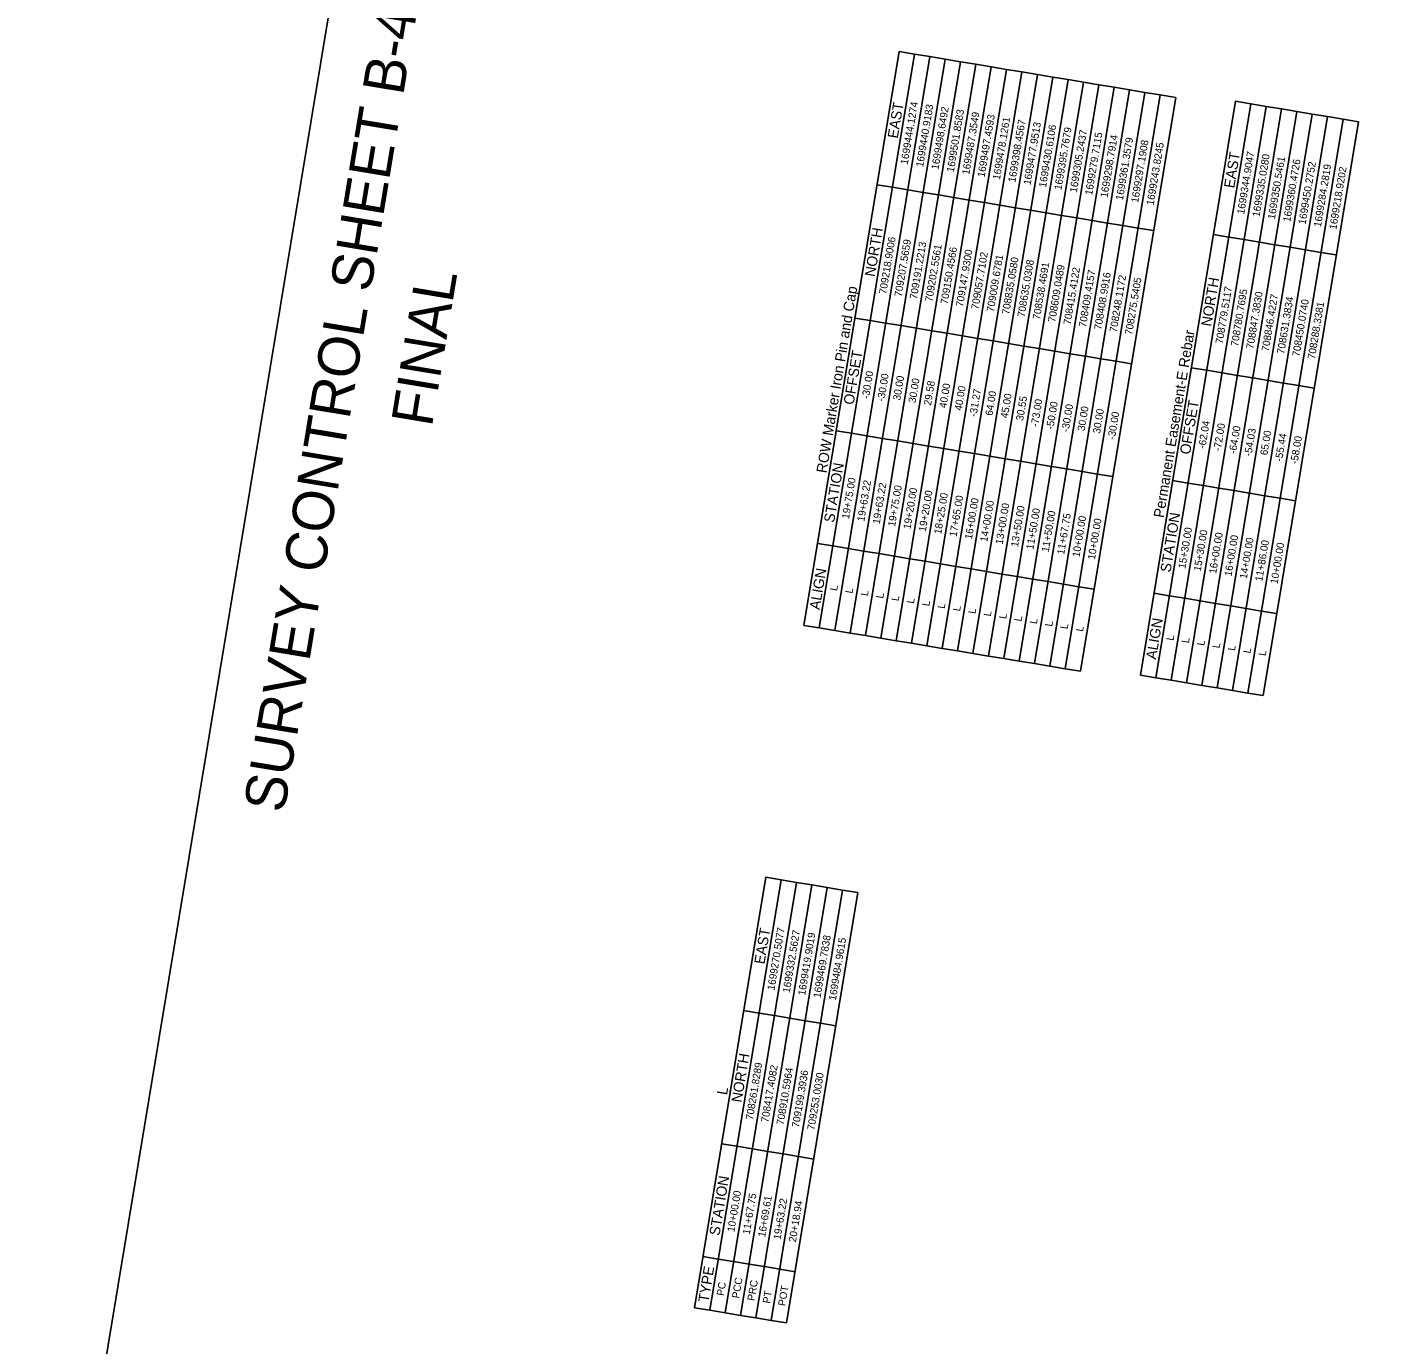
# Model space of a CAD drawing. Extents: x 1698609 to 1700392, y 707479 to 710040.
# Drawn here: x 1698609 to 1699524, y 708282 to 709170 of the extents above; entities that cross this region are included whole.
import ezdxf

# ---------------------------------------------------------------- set-up
doc = ezdxf.new("R2010")
doc.units = 0
for name, color, linetype in [('CTL Sheet Border CELL', 7, 'Continuous'), ('CTL Sheet Notes CELL', 7, 'Continuous'), ('CTL Sheet Table Cell', 7, 'Continuous'), ('CTL Sheet Text', 7, 'Continuous')]:
    doc.layers.add(name, color=color, linetype=linetype)

msp = doc.modelspace()

# ---------------------------------------------------------------- linework, layer by layer
at = {"layer": 'CTL Sheet Border CELL'}
msp.add_lwpolyline([(1698950.4, 710011.31), (1698609.09, 707952.45), (1700050.28, 707713.53), (1700391.59, 709772.4)], close=True, dxfattribs=at)
at = {"layer": 'CTL Sheet Table Cell'}
for p, q in [((1699132.73, 708766.82), (1699196.83, 709153.54)), ((1699143.08, 708765.1), (1699207.19, 709151.82)), ((1699153.44, 708763.39), (1699217.55, 709150.11)), ((1699163.8, 708761.67), (1699227.91, 709148.39)), ((1699196.83, 709153.54), (1699207.19, 709151.82)), ((1699207.19, 709151.82), (1699217.55, 709150.11)), ((1699217.55, 709150.11), (1699227.91, 709148.39)), ((1699227.91, 709148.39), (1699238.27, 709146.67)), ((1699174.16, 708759.95), (1699238.27, 709146.67)), ((1699184.52, 708758.23), (1699248.63, 709144.96)), ((1699194.88, 708756.52), (1699258.99, 709143.24)), ((1699205.24, 708754.8), (1699269.35, 709141.52)), ((1699215.59, 708753.08), (1699279.7, 709139.8)), ((1699225.95, 708751.37), (1699290.06, 709138.09)), ((1699238.27, 709146.67), (1699248.63, 709144.96)), ((1699248.63, 709144.96), (1699258.99, 709143.24)), ((1699258.99, 709143.24), (1699269.35, 709141.52)), ((1699269.35, 709141.52), (1699279.7, 709139.8)), ((1699279.7, 709139.8), (1699290.06, 709138.09)), ((1699290.06, 709138.09), (1699300.42, 709136.37)), ((1699236.31, 708749.65), (1699300.42, 709136.37)), ((1699246.67, 708747.93), (1699310.78, 709134.65)), ((1699257.03, 708746.21), (1699321.14, 709132.94)), ((1699267.39, 708744.5), (1699331.5, 709131.22)), ((1699277.75, 708742.78), (1699341.86, 709129.5)), ((1699300.42, 709136.37), (1699310.78, 709134.65)), ((1699310.78, 709134.65), (1699321.14, 709132.94)), ((1699321.14, 709132.94), (1699331.5, 709131.22)), ((1699331.5, 709131.22), (1699341.86, 709129.5)), ((1699341.86, 709129.5), (1699352.21, 709127.78)), ((1699288.11, 708741.06), (1699352.21, 709127.78)), ((1699298.46, 708739.34), (1699362.57, 709126.07)), ((1699308.82, 708737.63), (1699372.93, 709124.35)), ((1699319.18, 708735.91), (1699383.29, 709122.63)), ((1699352.21, 709127.78), (1699362.57, 709126.07)), ((1699359.49, 708733.3), (1699423.6, 709120.02)), ((1699362.57, 709126.07), (1699372.93, 709124.35)), ((1699372.93, 709124.35), (1699383.29, 709122.63)), ((1699423.6, 709120.02), (1699433.96, 709118.31)), ((1699369.85, 708731.58), (1699433.96, 709118.31)), ((1699380.21, 708729.87), (1699444.32, 709116.59)), ((1699390.57, 708728.15), (1699454.68, 709114.87)), ((1699400.93, 708726.43), (1699465.04, 709113.15)), ((1699411.29, 708724.71), (1699475.39, 709111.44)), ((1699433.96, 709118.31), (1699444.32, 709116.59)), ((1699444.32, 709116.59), (1699454.68, 709114.87)), ((1699454.68, 709114.87), (1699465.04, 709113.15)), ((1699465.04, 709113.15), (1699475.39, 709111.44)), ((1699475.39, 709111.44), (1699485.75, 709109.72)), ((1699421.64, 708723), (1699485.75, 709109.72)), ((1699432, 708721.28), (1699496.11, 709108)), ((1699442.36, 708719.56), (1699506.47, 709106.28)), ((1699485.75, 709109.72), (1699496.11, 709108)), ((1699496.11, 709108), (1699506.47, 709106.28)), ((1699181.95, 709063.77), (1699192.31, 709062.05)), ((1699192.31, 709062.05), (1699202.67, 709060.33)), ((1699202.67, 709060.33), (1699213.03, 709058.62)), ((1699213.03, 709058.62), (1699223.39, 709056.9)), ((1699223.39, 709056.9), (1699233.75, 709055.18)), ((1699233.75, 709055.18), (1699244.1, 709053.46)), ((1699244.1, 709053.46), (1699254.46, 709051.75)), ((1699254.46, 709051.75), (1699264.82, 709050.03)), ((1699264.82, 709050.03), (1699275.18, 709048.31)), ((1699275.18, 709048.31), (1699285.54, 709046.6)), ((1699285.54, 709046.6), (1699295.9, 709044.88)), ((1699295.9, 709044.88), (1699306.26, 709043.16)), ((1699306.26, 709043.16), (1699316.61, 709041.44)), ((1699316.61, 709041.44), (1699326.97, 709039.73)), ((1699326.97, 709039.73), (1699337.33, 709038.01)), ((1699337.33, 709038.01), (1699347.69, 709036.29)), ((1699347.69, 709036.29), (1699358.05, 709034.57)), ((1699358.05, 709034.57), (1699368.41, 709032.86)), ((1699408.72, 709030.25), (1699419.08, 709028.53)), ((1699419.08, 709028.53), (1699429.44, 709026.81)), ((1699429.44, 709026.81), (1699439.79, 709025.1)), ((1699439.79, 709025.1), (1699450.15, 709023.38)), ((1699450.15, 709023.38), (1699460.51, 709021.66)), ((1699460.51, 709021.66), (1699470.87, 709019.94)), ((1699470.87, 709019.94), (1699481.23, 709018.23)), ((1699481.23, 709018.23), (1699491.59, 709016.51)), ((1699167.07, 708973.99), (1699177.43, 708972.28)), ((1699177.43, 708972.28), (1699187.79, 708970.56)), ((1699187.79, 708970.56), (1699198.15, 708968.84)), ((1699198.15, 708968.84), (1699208.5, 708967.12)), ((1699208.5, 708967.12), (1699218.86, 708965.41)), ((1699218.86, 708965.41), (1699229.22, 708963.69)), ((1699229.22, 708963.69), (1699239.58, 708961.97)), ((1699239.58, 708961.97), (1699249.94, 708960.25)), ((1699249.94, 708960.25), (1699260.3, 708958.54)), ((1699260.3, 708958.54), (1699270.66, 708956.82)), ((1699270.66, 708956.82), (1699281.01, 708955.1)), ((1699281.01, 708955.1), (1699291.37, 708953.39)), ((1699291.37, 708953.39), (1699301.73, 708951.67)), ((1699301.73, 708951.67), (1699312.09, 708949.95)), ((1699312.09, 708949.95), (1699322.45, 708948.23)), ((1699322.45, 708948.23), (1699332.81, 708946.52)), ((1699332.81, 708946.52), (1699343.17, 708944.8)), ((1699343.17, 708944.8), (1699353.53, 708943.08)), ((1699393.84, 708940.47), (1699404.19, 708938.76)), ((1699404.19, 708938.76), (1699414.55, 708937.04)), ((1699414.55, 708937.04), (1699424.91, 708935.32)), ((1699424.91, 708935.32), (1699435.27, 708933.6)), ((1699435.27, 708933.6), (1699445.63, 708931.89)), ((1699445.63, 708931.89), (1699455.99, 708930.17)), ((1699455.99, 708930.17), (1699466.35, 708928.45)), ((1699466.35, 708928.45), (1699476.71, 708926.74)), ((1699154.48, 708898.03), (1699164.84, 708896.31)), ((1699164.84, 708896.31), (1699175.19, 708894.59)), ((1699175.19, 708894.59), (1699185.55, 708892.88)), ((1699185.55, 708892.88), (1699195.91, 708891.16)), ((1699195.91, 708891.16), (1699206.27, 708889.44)), ((1699206.27, 708889.44), (1699216.63, 708887.73)), ((1699216.63, 708887.73), (1699226.99, 708886.01)), ((1699226.99, 708886.01), (1699237.35, 708884.29)), ((1699237.35, 708884.29), (1699247.7, 708882.57)), ((1699247.7, 708882.57), (1699258.06, 708880.86)), ((1699258.06, 708880.86), (1699268.42, 708879.14)), ((1699268.42, 708879.14), (1699278.78, 708877.42)), ((1699278.78, 708877.42), (1699289.14, 708875.71)), ((1699289.14, 708875.71), (1699299.5, 708873.99)), ((1699299.5, 708873.99), (1699309.86, 708872.27)), ((1699309.86, 708872.27), (1699320.22, 708870.55)), ((1699320.22, 708870.55), (1699330.57, 708868.84)), ((1699330.57, 708868.84), (1699340.93, 708867.12)), ((1699381.24, 708864.51), (1699391.6, 708862.79)), ((1699391.6, 708862.79), (1699401.96, 708861.08)), ((1699401.96, 708861.08), (1699412.32, 708859.36)), ((1699412.32, 708859.36), (1699422.68, 708857.64)), ((1699422.68, 708857.64), (1699433.04, 708855.92)), ((1699433.04, 708855.92), (1699443.4, 708854.21)), ((1699443.4, 708854.21), (1699453.75, 708852.49)), ((1699453.75, 708852.49), (1699464.11, 708850.77)), ((1699141.88, 708822.07), (1699152.24, 708820.35)), ((1699152.24, 708820.35), (1699162.6, 708818.63)), ((1699162.6, 708818.63), (1699172.96, 708816.91)), ((1699172.96, 708816.91), (1699183.32, 708815.2)), ((1699183.32, 708815.2), (1699193.68, 708813.48)), ((1699193.68, 708813.48), (1699204.04, 708811.76)), ((1699204.04, 708811.76), (1699214.39, 708810.05)), ((1699214.39, 708810.05), (1699224.75, 708808.33)), ((1699224.75, 708808.33), (1699235.11, 708806.61)), ((1699235.11, 708806.61), (1699245.47, 708804.89)), ((1699245.47, 708804.89), (1699255.83, 708803.18)), ((1699255.83, 708803.18), (1699266.19, 708801.46)), ((1699266.19, 708801.46), (1699276.55, 708799.74)), ((1699276.55, 708799.74), (1699286.9, 708798.03)), ((1699286.9, 708798.03), (1699297.26, 708796.31)), ((1699297.26, 708796.31), (1699307.62, 708794.59)), ((1699307.62, 708794.59), (1699317.98, 708792.87)), ((1699317.98, 708792.87), (1699328.34, 708791.16)), ((1699368.65, 708788.55), (1699379.01, 708786.83)), ((1699379.01, 708786.83), (1699389.37, 708785.11)), ((1699389.37, 708785.11), (1699399.73, 708783.39)), ((1699399.73, 708783.39), (1699410.09, 708781.68)), ((1699410.09, 708781.68), (1699420.44, 708779.96)), ((1699420.44, 708779.96), (1699430.8, 708778.24)), ((1699430.8, 708778.24), (1699441.16, 708776.53)), ((1699441.16, 708776.53), (1699451.52, 708774.81)), ((1699132.73, 708766.82), (1699143.08, 708765.1)), ((1699143.08, 708765.1), (1699153.44, 708763.39)), ((1699153.44, 708763.39), (1699163.8, 708761.67)), ((1699163.8, 708761.67), (1699174.16, 708759.95)), ((1699174.16, 708759.95), (1699184.52, 708758.23)), ((1699184.52, 708758.23), (1699194.88, 708756.52)), ((1699194.88, 708756.52), (1699205.24, 708754.8)), ((1699205.24, 708754.8), (1699215.59, 708753.08)), ((1699215.59, 708753.08), (1699225.95, 708751.37)), ((1699225.95, 708751.37), (1699236.31, 708749.65)), ((1699236.31, 708749.65), (1699246.67, 708747.93)), ((1699246.67, 708747.93), (1699257.03, 708746.21)), ((1699257.03, 708746.21), (1699267.39, 708744.5)), ((1699267.39, 708744.5), (1699277.75, 708742.78)), ((1699277.75, 708742.78), (1699288.11, 708741.06)), ((1699288.11, 708741.06), (1699298.46, 708739.34)), ((1699298.46, 708739.34), (1699308.82, 708737.63)), ((1699308.82, 708737.63), (1699319.18, 708735.91)), ((1699359.49, 708733.3), (1699369.85, 708731.58)), ((1699369.85, 708731.58), (1699380.21, 708729.87)), ((1699380.21, 708729.87), (1699390.57, 708728.15)), ((1699390.57, 708728.15), (1699400.93, 708726.43)), ((1699400.93, 708726.43), (1699411.29, 708724.71)), ((1699411.29, 708724.71), (1699421.64, 708723)), ((1699421.64, 708723), (1699432, 708721.28)), ((1699432, 708721.28), (1699442.36, 708719.56)), ((1699058.91, 708307.02), (1699106.95, 708597.07)), ((1699069.26, 708305.31), (1699117.31, 708595.35)), ((1699079.62, 708303.59), (1699127.67, 708593.64)), ((1699089.98, 708301.87), (1699138.02, 708591.92)), ((1699100.34, 708300.16), (1699148.38, 708590.21)), ((1699106.95, 708597.07), (1699117.31, 708595.35)), ((1699117.31, 708595.35), (1699127.67, 708593.64)), ((1699127.67, 708593.64), (1699138.02, 708591.92)), ((1699138.02, 708591.92), (1699148.38, 708590.21)), ((1699148.38, 708590.21), (1699158.74, 708588.49)), ((1699110.7, 708298.44), (1699158.74, 708588.49)), ((1699121.06, 708296.73), (1699169.1, 708586.77)), ((1699158.74, 708588.49), (1699169.1, 708586.77)), ((1699092.08, 708507.29), (1699102.44, 708505.58)), ((1699102.44, 708505.58), (1699112.8, 708503.86)), ((1699112.8, 708503.86), (1699123.15, 708502.15)), ((1699123.15, 708502.15), (1699133.51, 708500.43)), ((1699133.51, 708500.43), (1699143.87, 708498.71)), ((1699143.87, 708498.71), (1699154.23, 708497)), ((1699077.21, 708417.52), (1699087.57, 708415.8)), ((1699087.57, 708415.8), (1699097.93, 708414.08)), ((1699097.93, 708414.08), (1699108.28, 708412.37)), ((1699108.28, 708412.37), (1699118.64, 708410.65)), ((1699118.64, 708410.65), (1699129, 708408.94)), ((1699129, 708408.94), (1699139.36, 708407.22)), ((1699064.63, 708341.55), (1699074.98, 708339.83)), ((1699074.98, 708339.83), (1699085.34, 708338.12)), ((1699085.34, 708338.12), (1699095.7, 708336.4)), ((1699095.7, 708336.4), (1699106.06, 708334.69)), ((1699106.06, 708334.69), (1699116.42, 708332.97)), ((1699116.42, 708332.97), (1699126.78, 708331.26)), ((1699058.91, 708307.02), (1699069.26, 708305.31)), ((1699069.26, 708305.31), (1699079.62, 708303.59)), ((1699079.62, 708303.59), (1699089.98, 708301.87)), ((1699089.98, 708301.87), (1699100.34, 708300.16)), ((1699100.34, 708300.16), (1699110.7, 708298.44)), ((1699110.7, 708298.44), (1699121.06, 708296.73))]:
    msp.add_line(p, q, dxfattribs=at)

# ---------------------------------------------------------------- texts
at = {"layer": 'CTL Sheet Border CELL'}
for s, height, p in [('SURVEY CONTROL SHEET B-4799', 27.8261, (1698782.33, 708639.88)), ('FINAL', 27.826, (1698881.86, 708899.95))]:
    msp.add_text(s, height=height, rotation=80.58737, dxfattribs=at).set_placement(p)
at = {"layer": 'CTL Sheet Notes CELL'}
for s, rotation, p in [('EAST', 80.58737, (1699195.94, 709094.66)), ('EAST', 80.58737, (1699422.71, 709061.14)), ('NORTH', 80.58737, (1699180.49, 709001.46)), ('NORTH', 80.58737, (1699407.26, 708967.94)), ('ROW Marker Iron Pin and Cap', 80.58737, (1699147.91, 708869.12)), ('Permanent Easement-E Rebar', 80.58737, (1699375.24, 708839.02)), ('OFFSET', 80.58737, (1699166.19, 708915.17)), ('OFFSET', 80.58737, (1699392.95, 708881.65)), ('STATION', 80.58737, (1699153.03, 708835.78)), ('STATION', 80.58737, (1699379.79, 708802.26)), ('ALIGN', 80.58737, (1699143.29, 708777.03)), ('ALIGN', 80.58737, (1699370.05, 708743.51)), ('EAST', 80.59521, (1699106.06, 708538.19)), ('NORTH', 80.59521, (1699090.63, 708444.99)), ('L', 80.59521, (1699080.82, 708450.05)), ('STATION', 80.59521, (1699075.77, 708355.26)), ('TYPE', 80.59521, (1699068.32, 708310.29))]:
    msp.add_text(s, height=7, rotation=rotation, dxfattribs=at).set_placement(p)
at = {"layer": 'CTL Sheet Text'}
for s, rotation, p in [('1699444.1274', 80.58737, (1699202.67, 709077.12)), ('1699440.9183', 80.58737, (1699213.02, 709075.41)), ('1699498.6492', 80.58737, (1699223.38, 709073.69)), ('1699501.8583', 80.58737, (1699233.74, 709071.97)), ('1699487.3549', 80.58737, (1699244.1, 709070.25)), ('1699497.4593', 80.58737, (1699254.46, 709068.54)), ('1699478.1261', 80.58737, (1699264.82, 709066.82)), ('1699398.4567', 80.58737, (1699275.18, 709065.1)), ('1699477.9513', 80.58737, (1699285.53, 709063.39)), ('1699430.6106', 80.58737, (1699295.89, 709061.67)), ('1699395.7679', 80.58737, (1699306.25, 709059.95)), ('1699305.2437', 80.58737, (1699316.61, 709058.23)), ('1699279.7115', 80.58737, (1699326.97, 709056.52)), ('1699298.7914', 80.58737, (1699337.33, 709054.8)), ('1699361.3579', 80.58737, (1699347.69, 709053.08)), ('1699297.1908', 80.58737, (1699358.04, 709051.36)), ('1699243.8245', 80.58737, (1699368.4, 709049.65)), ('1699344.9047', 80.58737, (1699429.43, 709043.6)), ('1699335.0280', 80.58737, (1699439.79, 709041.89)), ('1699350.5461', 80.58737, (1699450.15, 709040.17)), ('1699360.4726', 80.58737, (1699460.51, 709038.45)), ('1699450.2752', 80.58737, (1699470.87, 709036.73)), ('1699284.2819', 80.58737, (1699481.22, 709035.02)), ('1699218.9202', 80.58737, (1699491.58, 709033.3)), ('709218.9006', 80.58737, (1699188.19, 708989.79)), ('709207.5659', 80.58737, (1699198.55, 708988.08)), ('709191.2213', 80.58737, (1699208.91, 708986.36)), ('709202.5561', 80.58737, (1699219.26, 708984.64)), ('709150.4566', 80.58737, (1699229.62, 708982.93)), ('709147.9300', 80.58737, (1699239.98, 708981.21)), ('709057.7102', 80.58737, (1699250.34, 708979.49)), ('709009.6781', 80.58737, (1699260.7, 708977.77)), ('708835.0580', 80.58737, (1699271.06, 708976.06)), ('708635.0308', 80.58737, (1699281.42, 708974.34)), ('708538.4691', 80.58737, (1699291.77, 708972.62)), ('708609.0489', 80.58737, (1699302.13, 708970.91)), ('708415.4122', 80.58737, (1699312.49, 708969.19)), ('708409.4157', 80.58737, (1699322.85, 708967.47)), ('708408.9916', 80.58737, (1699333.21, 708965.75)), ('708248.1172', 80.58737, (1699343.57, 708964.04)), ('708275.5405', 80.58737, (1699353.93, 708962.32)), ('708779.5117', 80.58737, (1699414.96, 708956.28)), ('708780.7695', 80.58737, (1699425.31, 708954.56)), ('708847.3830', 80.58737, (1699435.67, 708952.84)), ('708846.4227', 80.58737, (1699446.03, 708951.12)), ('708631.3834', 80.58737, (1699456.39, 708949.41)), ('708450.0740', 80.58737, (1699466.75, 708947.69)), ('708288.3381', 80.58737, (1699477.11, 708945.97)), ('-30.00', 80.58737, (1699176.48, 708919.16)), ('-30.00', 80.58737, (1699186.84, 708917.44)), ('30.00', 80.58737, (1699197.6, 708918.17)), ('30.00', 80.58737, (1699207.96, 708916.46)), ('29.58', 80.58737, (1699218.32, 708914.74)), ('40.00', 80.58737, (1699228.68, 708913.02)), ('40.00', 80.58737, (1699239.04, 708911.3)), ('-31.27', 80.58737, (1699248.99, 708907.14)), ('64.00', 80.58737, (1699259.75, 708907.87)), ('45.00', 80.58737, (1699270.11, 708906.15)), ('30.55', 80.58737, (1699280.47, 708904.44)), ('-73.00', 80.58737, (1699290.42, 708900.27)), ('-50.00', 80.58737, (1699300.78, 708898.55)), ('-30.00', 80.58737, (1699311.14, 708896.84)), ('30.00', 80.58737, (1699321.91, 708897.57)), ('30.00', 80.58737, (1699332.26, 708895.85)), ('-30.00', 80.58737, (1699342.22, 708891.69)), ('-62.04', 80.58737, (1699403.25, 708885.64)), ('-72.00', 80.58737, (1699413.6, 708883.92)), ('-64.00', 80.58737, (1699423.96, 708882.21)), ('-54.03', 80.58737, (1699434.32, 708880.49)), ('65.00', 80.58737, (1699445.09, 708881.22)), ('-55.44', 80.58737, (1699455.04, 708877.05)), ('-58.00', 80.58737, (1699465.4, 708875.34)), ('19+75.00', 80.58737, (1699163.07, 708838.3)), ('19+63.22', 80.58737, (1699173.43, 708836.59)), ('19+63.22', 80.58737, (1699183.79, 708834.87)), ('19+75.00', 80.58737, (1699194.15, 708833.15)), ('19+20.00', 80.58737, (1699204.51, 708831.43)), ('19+20.00', 80.58737, (1699214.87, 708829.72)), ('18+25.00', 80.58737, (1699225.23, 708828)), ('17+65.00', 80.58737, (1699235.59, 708826.28)), ('16+00.00', 80.58737, (1699245.94, 708824.57)), ('14+00.00', 80.58737, (1699256.3, 708822.85)), ('13+00.00', 80.58737, (1699266.66, 708821.13)), ('13+50.00', 80.58737, (1699277.02, 708819.41)), ('11+50.00', 80.58737, (1699287.38, 708817.7)), ('11+50.00', 80.58737, (1699297.74, 708815.98)), ('11+67.75', 80.58737, (1699308.1, 708814.26)), ('10+00.00', 80.58737, (1699318.45, 708812.55)), ('10+00.00', 80.58737, (1699328.81, 708810.83)), ('15+30.00', 80.58737, (1699389.84, 708804.78)), ('15+30.00', 80.58737, (1699400.2, 708803.07)), ('16+00.00', 80.58737, (1699410.56, 708801.35)), ('16+00.00', 80.58737, (1699420.92, 708799.63)), ('14+00.00', 80.58737, (1699431.28, 708797.91)), ('11+86.00', 80.58737, (1699441.63, 708796.2)), ('10+00.00', 80.58737, (1699451.99, 708794.48)), ('L', 80.58737, (1699155.04, 708789.83)), ('L', 80.58737, (1699165.4, 708788.11)), ('L', 80.58737, (1699175.76, 708786.39)), ('L', 80.58737, (1699186.11, 708784.68)), ('L', 80.58737, (1699196.47, 708782.96)), ('L', 80.58737, (1699206.83, 708781.24)), ('L', 80.58737, (1699217.19, 708779.52)), ('L', 80.58737, (1699227.55, 708777.81)), ('L', 80.58737, (1699237.91, 708776.09)), ('L', 80.58737, (1699248.27, 708774.37)), ('L', 80.58737, (1699258.63, 708772.65)), ('L', 80.58737, (1699268.98, 708770.94)), ('L', 80.58737, (1699279.34, 708769.22)), ('L', 80.58737, (1699289.7, 708767.5)), ('L', 80.58737, (1699300.06, 708765.79)), ('L', 80.58737, (1699310.42, 708764.07)), ('L', 80.58737, (1699320.78, 708762.35)), ('L', 80.58737, (1699381.81, 708756.31)), ('L', 80.58737, (1699392.16, 708754.59)), ('L', 80.58737, (1699402.52, 708752.87)), ('L', 80.58737, (1699412.88, 708751.16)), ('L', 80.58737, (1699423.24, 708749.44)), ('L', 80.58737, (1699433.6, 708747.72)), ('L', 80.58737, (1699443.96, 708746)), ('1699270.5077', 80.59521, (1699112.79, 708520.65)), ('1699332.5627', 80.59521, (1699123.15, 708518.93)), ('1699419.9019', 80.59521, (1699133.51, 708517.22)), ('1699469.7838', 80.59521, (1699143.87, 708515.5)), ('1699484.9615', 80.59521, (1699154.22, 708513.79)), ('708261.8289', 80.59521, (1699098.32, 708433.32)), ('708417.4082', 80.59521, (1699108.68, 708431.6)), ('708910.5964', 80.59521, (1699119.04, 708429.89)), ('709199.3936', 80.59521, (1699129.4, 708428.17)), ('709253.0030', 80.59521, (1699139.76, 708426.46)), ('10+00.00', 80.59521, (1699085.81, 708357.79)), ('11+67.75', 80.59521, (1699096.17, 708356.07)), ('16+69.61', 80.59521, (1699106.53, 708354.36)), ('19+63.22', 80.59521, (1699116.89, 708352.64)), ('20+18.94', 80.59521, (1699127.25, 708350.93)), ('PC ', 80.59521, (1699078.69, 708314.78)), ('PCC', 80.59521, (1699089.05, 708313.06)), ('PRC', 80.59521, (1699099.41, 708311.35)), ('PT ', 80.59521, (1699109.77, 708309.63)), ('POT', 80.59521, (1699120.13, 708307.92))]:
    msp.add_text(s, height=5, rotation=rotation, dxfattribs=at).set_placement(p)

doc.saveas('drawing.dxf')
